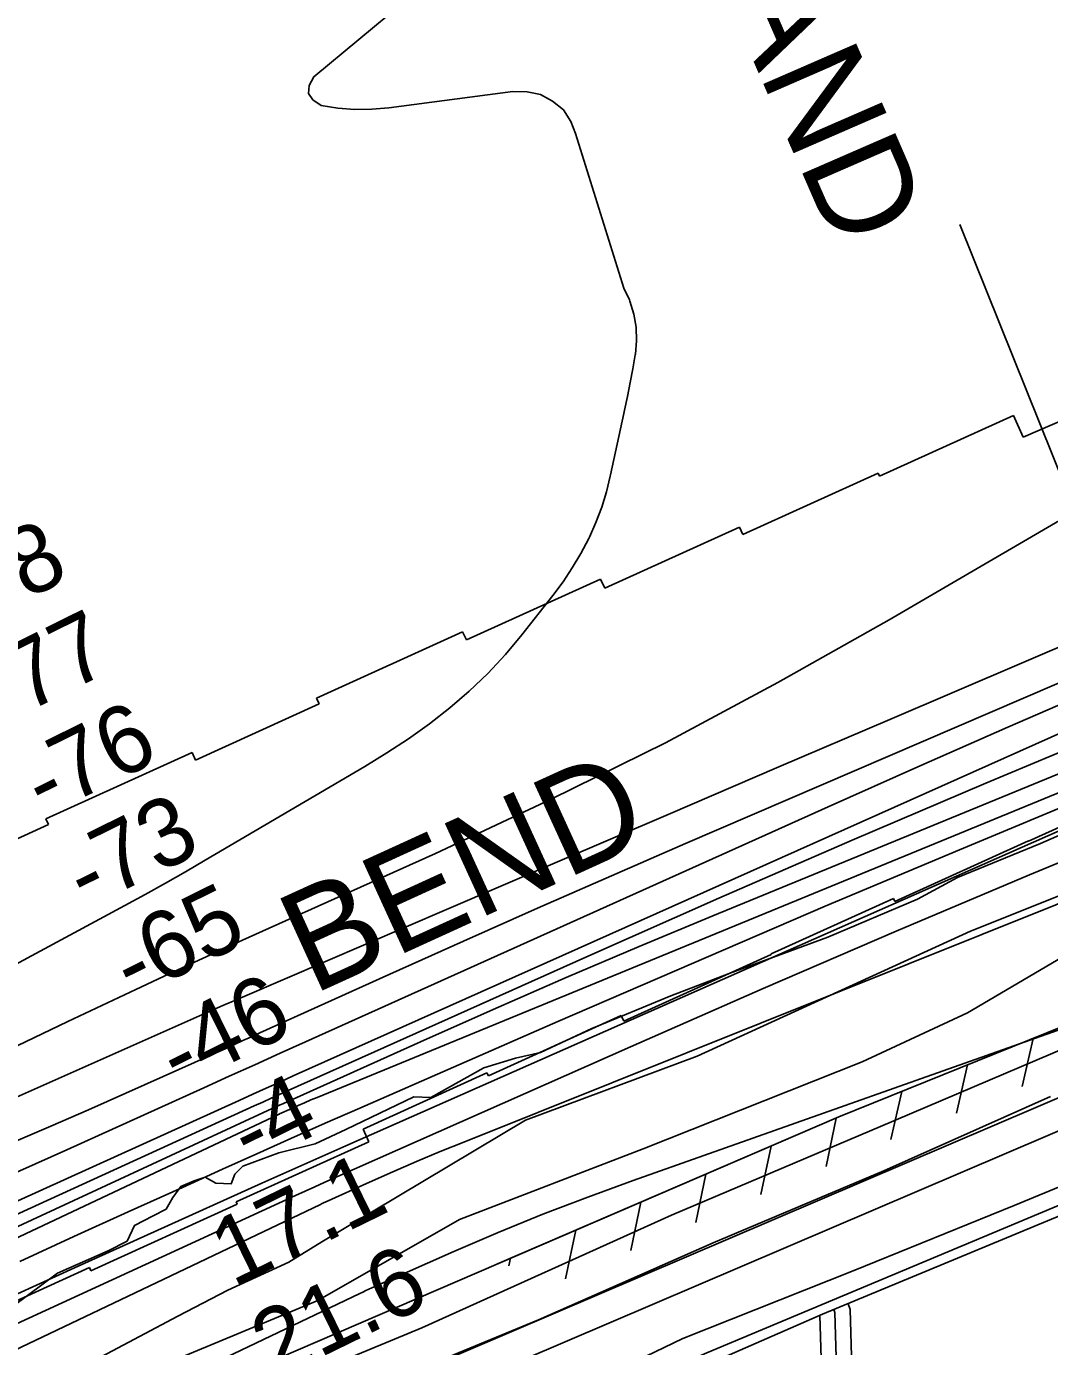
# Model space of a CAD drawing. Extents: x 3508733 to 3546731, y 546897 to 572481.
# Drawn here: x 3515521 to 3516531, y 562413 to 563717 of the extents above; entities that cross this region are included whole.
import ezdxf

# ---------------------------------------------------------------- set-up
doc = ezdxf.new("R2010")
doc.units = 0
for name, color, linetype in [('V-CHAN-NAID', 7, 'Continuous'), ('V-FLOD-BASE', 7, 'Continuous'), ('V-LEVE-TOET', 7, 'Continuous'), ('V-RIVR-EDGE', 7, 'Continuous'), ('V-RIVR-RANG', 7, 'Continuous'), ('V-ROAD-CNTR', 7, 'Continuous'), ('V-RRAP-FSHR', 7, 'Continuous'), ('V-RRAP-RVMT', 7, 'Continuous'), ('V-RRAP-RVMT-IDEN', 7, 'Continuous'), ('V-SITE-VEGE', 7, 'Continuous'), ('V-SURV-LINE', 7, 'Continuous'), ('V-TOPO-DPTH', 7, 'Continuous'), ('V-TOPO-MAJR', 7, 'Continuous'), ('V-TOPO-MINR', 7, 'Continuous'), ('V-TOPO-SHOR', 7, 'Continuous'), ('V-TOPO-WATR', 7, 'Continuous')]:
    doc.layers.add(name, color=color, linetype=linetype)

msp = doc.modelspace()

# ---------------------------------------------------------------- linework, layer by layer
at = {"layer": 'V-FLOD-BASE'}
msp.add_lwpolyline([(3515655, 562293), (3515655, 562295.4), (3515641.8, 562324.2), (3515645.9, 562330.7), (3515653, 562331.3), (3515657.7, 562328.4), (3515669.7, 562300.2), (3515693.8, 562305.6), (3515736.2, 562315.3), (3515766.2, 562327.8), (3515822.7, 562353.5), (3515932.7, 562400.2), (3516026.8, 562439.1), (3516199.2, 562515), (3516367.4, 562586.1), (3516532.1, 562659.6)], dxfattribs=at)
at = {"layer": 'V-LEVE-TOET'}
for points in [[(3513642.8, 561234.3), (3513826.8, 561342.7), (3514096.5, 561510.6), (3514311.6, 561641.6), (3514557.8, 561788.7), (3514864.6, 561974.5), (3514934.5, 562015.6), (3514978, 562035.9), (3515088.1, 562076.6), (3515256.8, 562157.2), (3515483.3, 562255.2), (3515628.6, 562328), (3515649.1, 562342.3), (3515657.3, 562346.5), (3515678.6, 562346), (3515707.4, 562351.5), (3515731, 562357.5), (3515757.5, 562367.1), (3515911.6, 562431.1), (3516158.1, 562542.2), (3516377.5, 562635.5), (3516658.1, 562755.1)], [(3514003.2, 561289), (3514121.9, 561355.8), (3514325.2, 561478.4), (3514550.3, 561623), (3514707.1, 561728.3), (3514798.2, 561783.1), (3514917.5, 561854), (3515032.7, 561918.9), (3515100.9, 561946.5), (3515177.4, 561982.3), (3515244.5, 562011.6), (3515339.2, 562051.7), (3515478.5, 562118.5), (3515649.7, 562189.7), (3515728.6, 562215.5), (3515762.1, 562231), (3515881, 562283.6), (3516050.3, 562363.1), (3516169.1, 562420.4), (3516337.4, 562487.4), (3516496.2, 562552), (3516699.2, 562635.7)]]:
    msp.add_lwpolyline(points, dxfattribs=at)
at = {"layer": 'V-RIVR-EDGE'}
for points in [[(3516004.1, 562697.5), (3516028.7, 562702.9), (3516079.2, 562726.7), (3516157.3, 562759), (3516215, 562781), (3516312.4, 562816.8), (3516400.7, 562854.4), (3516440.4, 562875.9), (3516522.1, 562909.3), (3516641.7, 562961.9)], [(3515508.2, 562452.6), (3515552.1, 562484.9), (3515602, 562507), (3515620.6, 562516.6), (3515627.9, 562532.2), (3515646.5, 562541.7), (3515659.1, 562548.3), (3515665.8, 562559.7), (3515673.6, 562570.5), (3515686.8, 562576.4), (3515697.6, 562580), (3515708.4, 562574), (3515723.4, 562573.3), (3515727.1, 562582.9), (3515734.9, 562590.7), (3515770.3, 562603.8), (3515806.4, 562612.8), (3515836.4, 562627.1), (3515903.7, 562659.3), (3515920.6, 562658.7), (3515972.9, 562688), (3516004.1, 562697.5)]]:
    msp.add_lwpolyline(points, dxfattribs=at)
at = {"layer": 'V-RIVR-RANG'}
msp.add_line((3516755.3, 562741.5), (3516442.4, 563521), dxfattribs=at)
at = {"layer": 'V-ROAD-CNTR'}
for points in [[(3518185, 563177), (3518070.5, 563139.1), (3517881.5, 563064.1), (3517716.5, 563003.6), (3517371.7, 562868.5), (3516843.7, 562668.3), (3516559.9, 562549.6), (3516307, 562444.5), (3515895.5, 562264.3), (3515695.8, 562177), (3515359.6, 562027.6), (3515169.1, 561950.3), (3515006.8, 561875.8), (3514680.2, 561669.4), (3514432.2, 561519.5)], [(3516318.2, 562449.2), (3516319.3, 562446.3), (3516321.3, 562379.6), (3516326.2, 562221.6), (3516328.1, 562158.5), (3516335.6, 562143.5), (3516351.1, 562135.2), (3516383.4, 562134.9), (3516414.5, 562135.8), (3516441.9, 562136.9), (3516458.3, 562140.3)], [(3516332.2, 562454.6), (3516334.2, 562449.3), (3516336.3, 562380.1), (3516341.2, 562222.1), (3516343, 562162.3), (3516346.8, 562154.4), (3516354.9, 562150.1), (3516383.2, 562149.9), (3516414, 562150.8), (3516440.1, 562151.8), (3516455.3, 562155)], [(3516304.2, 562443.8), (3516304.4, 562443.4), (3516306.3, 562379.2), (3516311.2, 562221.2), (3516313.2, 562154.8), (3516324.3, 562132.5), (3516347.3, 562120.2), (3516383.6, 562119.9), (3516415, 562120.8), (3516443.7, 562121.9), (3516461.3, 562125.6)]]:
    msp.add_lwpolyline(points, dxfattribs=at)
at = {"layer": 'V-RRAP-FSHR'}
for p, q in [((3516515.1, 562717), (3516504.1, 562669.5)), ((3516450.2, 562690.8), (3516439.2, 562643.2)), ((3516385.3, 562664.6), (3516374.3, 562617)), ((3516320.4, 562638.3), (3516310.6, 562590.5)), ((3516256.2, 562610.6), (3516246.3, 562562.8)), ((3516191.9, 562582.9), (3516182, 562535)), ((3516127.6, 562555.1), (3516117.8, 562507.3)), ((3516063.4, 562527.4), (3516053.5, 562479.6)), ((3515999.1, 562499.7), (3515997.5, 562492.2))]:
    msp.add_line(p, q, dxfattribs=at)
for points in [[(3512861.8, 560815), (3513646.8, 561263.9), (3514508.5, 561793.8), (3515097.9, 562097.5), (3515670.4, 562357.8), (3516323, 562639.4), (3516750.7, 562812.2), (3516861, 562862.4), (3516910.1, 562722)], [(3515986.1, 562494.1), (3516323, 562639.4), (3516750.7, 562812.2), (3516851.8, 562858.2)]]:
    msp.add_lwpolyline(points, dxfattribs=at)
at = {"layer": 'V-RRAP-RVMT'}
for p, q in [((3516505.1, 563310.8), (3516627, 563363.5)), ((3516363.4, 563272.3), (3516495.5, 563332.2)), ((3516495.5, 563332.2), (3516505.1, 563310.8)), ((3516228.3, 563214.6), (3516362, 563275.3)), ((3516362, 563275.3), (3516363.4, 563272.3)), ((3516092.2, 563161.6), (3516225, 563221.9)), ((3516225, 563221.9), (3516228.3, 563214.6)), ((3515955.5, 563110.5), (3516088, 563170.7)), ((3516088, 563170.7), (3516092.2, 563161.6)), ((3515807.7, 563053.1), (3515951.8, 563118.6)), ((3515951.8, 563118.6), (3515955.5, 563110.5)), ((3515688.1, 562991.9), (3515810.3, 563047.4)), ((3515810.3, 563047.4), (3515807.7, 563053.1)), ((3515540.6, 562933.8), (3515684.8, 562999.3)), ((3515684.8, 562999.3), (3515688.1, 562991.9)), ((3516639.3, 562970.3), (3516510.4, 562911.8)), ((3515411.8, 562868.5), (3515543.1, 562928.1)), ((3515543.1, 562928.1), (3515540.6, 562933.8)), ((3516510.2, 562912.2), (3516378.3, 562852.3)), ((3516510.4, 562911.8), (3516510.2, 562912.2)), ((3516377, 562855.2), (3516256.2, 562800.4)), ((3516378.3, 562852.3), (3516377, 562855.2)), ((3516256.4, 562799.9), (3516110.8, 562733.9)), ((3516256.2, 562800.4), (3516256.4, 562799.9)), ((3516108.3, 562739.4), (3515977.2, 562679.9)), ((3516110.8, 562733.9), (3516108.3, 562739.4)), ((3515975.8, 562682.9), (3515853.6, 562627.4)), ((3515977.2, 562679.9), (3515975.8, 562682.9)), ((3515853.6, 562627.4), (3515859.3, 562614.9)), ((3515859.3, 562614.9), (3515728.4, 562555.4)), ((3515729.4, 562553.2), (3515584.8, 562487.5)), ((3515728.4, 562555.4), (3515729.4, 562553.2)), ((3515583.4, 562490.5), (3515449.8, 562429.8)), ((3515584.8, 562487.5), (3515583.4, 562490.5))]:
    msp.add_line(p, q, dxfattribs=at)
at = {"layer": 'V-SITE-VEGE'}
msp.add_lwpolyline([(3516543.7, 562797.3), (3516450, 562742.3), (3516346.1, 562693.8), (3516130, 562607.9), (3515948.8, 562538.2), (3515809, 562458.1), (3515385.7, 562282.2), (3515381, 562281.6), (3515379.2, 562282.2), (3515376.8, 562284), (3515375.6, 562286.3), (3515376.8, 562289.9), (3515380.3, 562292.9), (3515455.3, 562328.2), (3515670.6, 562442.5), (3515720.2, 562468.2), (3515780.4, 562495.8), (3515812.8, 562516.1), (3516013.9, 562636.2), (3516183.3, 562699.3), (3516453, 562822.8), (3516819.6, 562969.3)], dxfattribs=at)
at = {"layer": 'V-SURV-LINE'}
for points in [[(3514999.5, 561999.3), (3516866.9, 562798)], [(3516878.7, 562770.4), (3515011.3, 561971.7)]]:
    msp.add_lwpolyline(points, dxfattribs=at)
at = {"layer": 'V-TOPO-DPTH'}
for points in [[(3516806, 563182.4), (3516171.7, 562909.3), (3516098.6, 562877.5), (3516025.6, 562845.5), (3515952.8, 562813.1), (3515880.1, 562780.5), (3515751.7, 562722.3), (3515743.3, 562718.5), (3515734.9, 562714.7), (3515726.5, 562710.9), (3515718.1, 562707.1), (3515656.3, 562679.2), (3515619.5, 562662.7), (3515582.6, 562646.3), (3515545.5, 562630.3), (3515508.4, 562614.4)], [(3516806, 563182.4), (3516171.7, 562909.3), (3516098.6, 562877.5), (3516025.6, 562845.5), (3515952.8, 562813.1), (3515880.1, 562780.5), (3515751.7, 562722.3), (3515743.3, 562718.5), (3515734.9, 562714.7), (3515726.5, 562710.9), (3515718.1, 562707.1), (3515656.3, 562679.2), (3515619.5, 562662.7), (3515582.6, 562646.3), (3515545.5, 562630.3), (3515508.4, 562614.4)], [(3516831.8, 563098), (3516198.7, 562837.9), (3516126.2, 562807.7), (3516054, 562777), (3515982, 562745.6), (3515910.3, 562713.7), (3515774.9, 562652.6), (3515771, 562650.9), (3515767.1, 562649.1), (3515763.3, 562647.3), (3515759.4, 562645.6), (3515221.1, 562395.7), (3515081.4, 562330.3), (3514942.1, 562264.3), (3514803.3, 562197.3), (3514664.8, 562129.6), (3514430.6, 562014.1), (3514409.6, 562003.4), (3514388.7, 561992.3), (3514368.1, 561980.6), (3514347.8, 561968.5), (3514119.2, 561828.8), (3514008.2, 561760)], [(3514008.2, 561760), (3514119.2, 561828.8), (3514347.8, 561968.5), (3514368.1, 561980.6), (3514388.7, 561992.3), (3514409.6, 562003.4), (3514430.6, 562014.1), (3514664.8, 562129.6), (3514803.3, 562197.3), (3514942.1, 562264.3), (3515081.4, 562330.3), (3515221.1, 562395.7), (3515759.4, 562645.6), (3515763.3, 562647.3), (3515767.1, 562649.1), (3515771, 562650.9), (3515774.9, 562652.6), (3515910.3, 562713.7), (3515982, 562745.6), (3516054, 562777), (3516126.2, 562807.7), (3516198.7, 562837.9), (3516831.8, 563098)], [(3516578.8, 563063), (3516489.9, 563024.3), (3516401.2, 562985.1), (3516312.7, 562945.5), (3515796.8, 562713.5), (3515771.7, 562702.2), (3515746.6, 562690.9), (3515721.5, 562679.5), (3515696.5, 562668.2), (3515561.1, 562607), (3515468.2, 562565.4)], [(3515468.2, 562565.4), (3515561.1, 562607), (3515696.5, 562668.2), (3515721.5, 562679.5), (3515746.6, 562690.9), (3515771.7, 562702.2), (3515796.8, 562713.5), (3516312.7, 562945.5), (3516401.2, 562985.1), (3516489.9, 563024.3), (3516578.8, 563063)], [(3515463.1, 562534.1), (3515731.2, 562655.7), (3515744.6, 562661.8), (3515758, 562667.8), (3515771.3, 562673.8), (3515784.7, 562679.8), (3516548.2, 563021.4)], [(3515463.1, 562534.1), (3515731.2, 562655.7), (3515744.6, 562661.8), (3515758, 562667.8), (3515771.3, 562673.8), (3515784.7, 562679.8), (3516548.2, 563021.4)], [(3516574.9, 562958.6), (3516442.2, 562903.3), (3516309.7, 562847.4), (3516177.6, 562790.7), (3516045.7, 562733.5), (3515850.2, 562648), (3515816.3, 562633.1), (3515782.4, 562618.1), (3515748.6, 562602.9), (3515714.8, 562587.7), (3515675.2, 562569.8), (3515621.7, 562545.5), (3515568.2, 562521.2), (3515514.8, 562496.7)], [(3516574.9, 562958.6), (3516442.2, 562903.3), (3516309.7, 562847.4), (3516177.6, 562790.7), (3516045.7, 562733.5), (3515850.2, 562648), (3515816.3, 562633.1), (3515782.4, 562618.1), (3515748.6, 562602.9), (3515714.8, 562587.7), (3515675.2, 562569.8), (3515621.7, 562545.5), (3515568.2, 562521.2), (3515514.8, 562496.7)], [(3513960.6, 561609.5), (3514071.9, 561683.1), (3514184, 561755.6), (3514383.1, 561882.4), (3514407.1, 561897.1), (3514431.3, 561911.3), (3514456, 561924.7), (3514481, 561937.6), (3514771.3, 562081.9), (3514942.1, 562165.7), (3515113.3, 562248.6), (3515285.3, 562329.9), (3515457.7, 562410.2), (3515787, 562561.7), (3515796.4, 562566.1), (3515805.9, 562570.4), (3515815.3, 562574.6), (3515824.8, 562578.8), (3516117.4, 562708.7), (3516248.3, 562766.1), (3516379.6, 562822.8), (3516511.2, 562878.4), (3516643.2, 562933.2)]]:
    msp.add_lwpolyline(points, dxfattribs=at)
at = {"layer": 'V-TOPO-MAJR'}
msp.add_lwpolyline([(3513841.2, 561789.1), (3514299.3, 562058.1), (3514320.3, 562070.2), (3514341.4, 562082.1), (3514362.7, 562093.6), (3514384.1, 562105), (3514805.7, 562323.6), (3514955.3, 562399.4), (3515105.9, 562473.5), (3515257.8, 562544.8), (3515410.5, 562614.2), (3515697.9, 562741.7), (3515707.6, 562746), (3515717.4, 562750.3), (3515727.1, 562754.5), (3515736.9, 562758.7), (3515936, 562844.3), (3516045.3, 562891.3), (3516154.7, 562938.2), (3516264, 562985.1), (3516373.4, 563031.9), (3516763.5, 563199)], dxfattribs=at)
at = {"layer": 'V-TOPO-MINR'}
for points in [[(3514836.7, 562426.6), (3515618.5, 562848.2), (3515638.5, 562859.2), (3515658.4, 562870.2), (3515678.2, 562881.5), (3515697.8, 562892.9), (3515855.4, 562985.5), (3515877.1, 562998.9), (3515898.3, 563012.9), (3515919, 563027.8), (3515939.1, 563043.4), (3515958.4, 563060), (3515976.8, 563077.4), (3515994, 563096.1), (3516010.4, 563115.5), (3516041, 563154.4), (3516050.9, 563167.9), (3516060.1, 563181.7), (3516068.6, 563196), (3516076.4, 563210.8), (3516076.9, 563211.9), (3516083.4, 563226.5), (3516089.2, 563241.5), (3516093.8, 563256.8), (3516097.6, 563272.4), (3516097.8, 563273.5), (3516101, 563288.7), (3516104.2, 563304), (3516107.5, 563319.1), (3516110.8, 563334.3), (3516111.5, 563337.5), (3516114.5, 563351.1), (3516117.2, 563364.7), (3516119.8, 563378.4), (3516122.2, 563392.2), (3516122.3, 563392.7), (3516123.4, 563406.1), (3516123.1, 563419.3), (3516120.7, 563432.3), (3516116.9, 563445.2), (3516116.4, 563446.4), (3516110.9, 563457.9), (3516063.1, 563610.6), (3516058.7, 563622.6), (3516051.3, 563634.1), (3516040.4, 563642.8), (3516028.6, 563649.2), (3516015.4, 563651.8), (3516001.4, 563652.1), (3515879, 563636), (3515862.2, 563634.7), (3515845.5, 563634.4), (3515828.8, 563635.8), (3515812.2, 563638.4), (3515804.1, 563643.9), (3515799.6, 563650.3), (3515800.5, 563658.1), (3515805, 563666.8), (3515893.7, 563740.6)], [(3513490.6, 561602.8), (3514280.3, 562063.7), (3514307.5, 562079.3), (3514334.8, 562094.7), (3514362.3, 562109.7), (3514389.9, 562124.4), (3515299.2, 562602.6), (3515364.4, 562636.3), (3515429.9, 562669.5), (3515495.8, 562701.8), (3515562, 562733.5), (3515629.4, 562765.3), (3515662.1, 562780.7), (3515695, 562795.9), (3515727.9, 562810.9), (3515760.8, 562825.8), (3515924.9, 562899.6), (3516039.1, 562953.1), (3516152, 563009), (3516263, 563068.5), (3516372.9, 563130.4), (3516600.1, 563263.1)], [(3515508.4, 562614.4), (3515545.5, 562630.3), (3515582.6, 562646.3), (3515619.5, 562662.7), (3515656.3, 562679.2), (3515718.1, 562707.1), (3515726.5, 562710.9), (3515734.9, 562714.7), (3515743.3, 562718.5), (3515751.7, 562722.3), (3515880.1, 562780.5), (3515952.8, 562813.1), (3516025.6, 562845.5), (3516098.6, 562877.5), (3516171.7, 562909.3), (3516806, 563182.4)], [(3514008.2, 561760), (3514119.2, 561828.8), (3514347.8, 561968.5), (3514368.1, 561980.6), (3514388.7, 561992.3), (3514409.6, 562003.4), (3514430.6, 562014.1), (3514664.8, 562129.6), (3514803.3, 562197.3), (3514942.1, 562264.3), (3515081.4, 562330.3), (3515221.1, 562395.7), (3515759.4, 562645.6), (3515763.3, 562647.3), (3515767.1, 562649.1), (3515771, 562650.9), (3515774.9, 562652.6), (3515910.3, 562713.7), (3515982, 562745.6), (3516054, 562777), (3516126.2, 562807.7), (3516198.7, 562837.9), (3516831.8, 563098)], [(3514031.4, 561757.9), (3514121.5, 561814.9), (3514212, 561871.1), (3514364.1, 561964), (3514379.1, 561972.9), (3514394.3, 561981.6), (3514409.7, 561989.8), (3514425.3, 561997.8), (3514604.1, 562086.4), (3514709.3, 562138.2), (3514814.7, 562189.6), (3514920.4, 562240.4), (3515026.3, 562290.7), (3515770, 562641.8), (3515770.6, 562642.1), (3515771.2, 562642.3), (3515783.1, 562647.8), (3515789.4, 562650.6), (3515795.7, 562653.4), (3515802, 562656.1), (3515808.3, 562658.7), (3516854.6, 563088.9)], [(3515468.2, 562565.4), (3515561.1, 562607), (3515696.5, 562668.2), (3515721.5, 562679.5), (3515746.6, 562690.9), (3515771.7, 562702.2), (3515796.8, 562713.5), (3516312.7, 562945.5), (3516401.2, 562985.1), (3516489.9, 563024.3), (3516578.8, 563063)], [(3513922.5, 561722.9), (3514331.4, 561973), (3514357.1, 561988.2), (3514383.1, 562002.9), (3514409.4, 562016.9), (3514436, 562030.5), (3514722.2, 562170.8), (3514892.4, 562253.4), (3515063.1, 562335.1), (3515234.4, 562415.4), (3515406.2, 562494.8), (3515746.2, 562650.3), (3515754.5, 562654.1), (3515762.8, 562657.9), (3515771.2, 562661.6), (3515779.5, 562665.4), (3516073.5, 562797.2), (3516204.7, 562855.4), (3516336.2, 562912.8), (3516468.2, 562969), (3516600.6, 563024.5)], [(3515455.9, 562439.1), (3515568.9, 562490.2), (3515753.6, 562573.8), (3515774.3, 562583.1), (3515795, 562592.4), (3515815.8, 562601.6), (3515836.5, 562610.8), (3516785.8, 563030.2)], [(3515463.1, 562534.1), (3515731.2, 562655.7), (3515744.6, 562661.8), (3515758, 562667.8), (3515771.3, 562673.8), (3515784.7, 562679.8), (3516548.2, 563021.4)], [(3515037.5, 562183.9), (3515811.4, 562553), (3515812.6, 562553.6), (3515815.1, 562554.7), (3515816.3, 562555.3), (3515859.9, 562575), (3515883, 562585.2), (3515906.2, 562595.3), (3515929.5, 562605.1), (3515952.9, 562614.6), (3516902.6, 562995.4)], [(3513960.6, 561609.5), (3514071.9, 561683.1), (3514184, 561755.6), (3514383.1, 561882.4), (3514407.1, 561897.1), (3514431.3, 561911.3), (3514456, 561924.7), (3514481, 561937.6), (3514771.3, 562081.9), (3514942.1, 562165.7), (3515113.3, 562248.6), (3515285.3, 562329.9), (3515457.7, 562410.2), (3515787, 562561.7), (3515796.4, 562566.1), (3515805.9, 562570.4), (3515815.3, 562574.6), (3515824.8, 562578.8), (3516117.4, 562708.7), (3516248.3, 562766.1), (3516379.6, 562822.8), (3516511.2, 562878.4), (3516643.2, 562933.2)], [(3515052.2, 562083.6), (3515850.5, 562465), (3515853.4, 562466.4), (3515856.3, 562467.8), (3515859.2, 562469.1), (3515862.2, 562470.4), (3515943.3, 562506.3), (3515987, 562525.1), (3516031, 562543.2), (3516075.4, 562560.2), (3516120, 562576.6), (3516587, 562741.9)]]:
    msp.add_lwpolyline(points, dxfattribs=at)
at = {"layer": 'V-TOPO-SHOR'}
msp.add_lwpolyline([(3517567, 562963.6), (3517338, 562872.1), (3517029.6, 562753.4), (3516737.8, 562634.9), (3516192.8, 562406.3), (3515625.9, 562156.2), (3515170.9, 561961.3), (3515047.8, 561911.9), (3515022.9, 561899.9), (3514850.3, 561797.5), (3514483.3, 561563.4), (3514010.3, 561277.7), (3513615.4, 561047.9)], dxfattribs=at)
at = {"layer": 'V-TOPO-WATR'}
msp.add_lwpolyline([(3515514.8, 562496.7), (3515568.2, 562521.2), (3515621.7, 562545.5), (3515675.2, 562569.8), (3515714.8, 562587.7), (3515748.6, 562602.9), (3515782.4, 562618.1), (3515816.3, 562633.1), (3515850.2, 562648), (3516045.7, 562733.5), (3516177.6, 562790.7), (3516309.7, 562847.4), (3516442.2, 562903.3), (3516574.9, 562958.6)], dxfattribs=at)

# ---------------------------------------------------------------- texts
at = {"layer": 'V-CHAN-NAID'}
msp.add_text('MARATHON ASHLAND ', height=100, rotation=293.5466, dxfattribs=at).set_placement((3515748.5, 564807.3))
at = {"layer": 'V-RIVR-RANG'}
for s, rotation, p in [('-78', 26.3287, (3515449.8, 563114.7)), ('-77', 26.3287, (3515494.1, 563025.1)), ('-76', 26.3287, (3515538.5, 562935.4)), ('-73', 26.3287, (3515579.8, 562844.3)), ('-65', 26.3287, (3515625.8, 562755.5)), ('-46', 26.3287, (3515671.4, 562666.5)), ('-4', 26.3287, (3515741.8, 562589.7)), ('17.1', 26.0483, (3515725.2, 562470.6)), ('21.6', 26.0483, (3515765.5, 562379))]:
    msp.add_text(s, height=67, rotation=rotation, dxfattribs=at).set_placement(p)
at = {"layer": 'V-RRAP-RVMT-IDEN'}
msp.add_text('   BEND', height=100, rotation=24.565, dxfattribs=at).set_placement((3515702.2, 562713.3))

doc.saveas('drawing.dxf')
